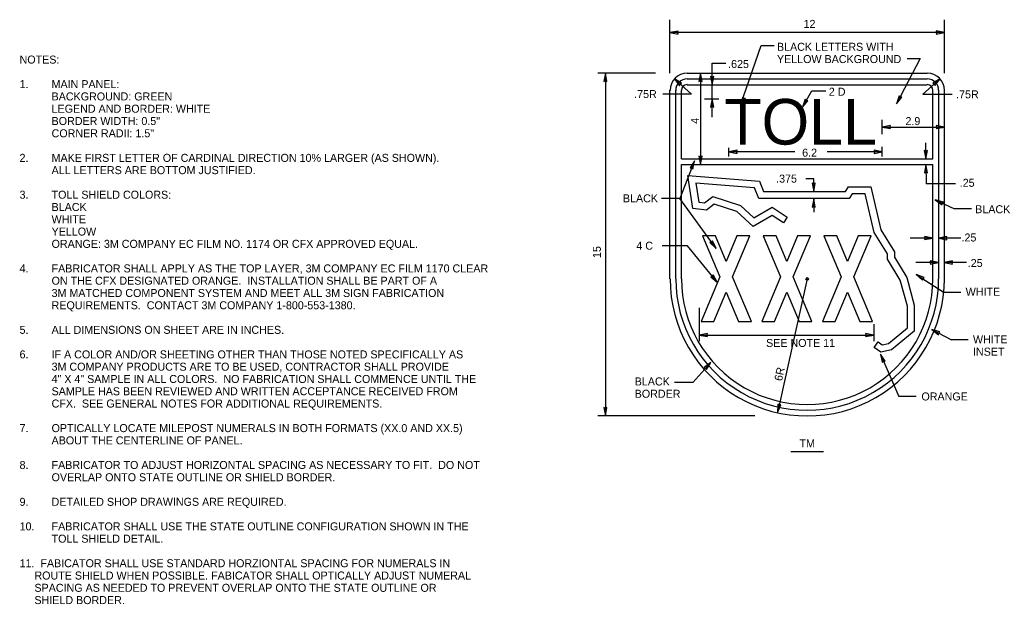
# Model space of a CAD drawing. Extents: x 56108 to 56734, y 11696 to 12110.
# Drawn here: x 56150 to 56496.4, y 11904.3 to 12108.8 of the extents above; entities that cross this region are included whole.
import ezdxf

# ---------------------------------------------------------------- set-up
doc = ezdxf.new("R2010")
doc.units = 0
for name, color, linetype in [('GSDims', 7, 'Continuous'), ('SignDetail', 7, 'Continuous'), ('SignPanel', 7, 'Continuous'), ('TextNotes', 7, 'Continuous')]:
    doc.layers.add(name, color=color, linetype=linetype)

msp = doc.modelspace()

# ---------------------------------------------------------------- linework, layer by layer
at = {"layer": 'GSDims'}
for p, q in [((56377.39, 12090.18), (56377.39, 12108.84)), ((56473.39, 12090.18), (56473.39, 12108.84)), ((56380.29, 12104.92), (56377.39, 12104.38)), ((56473.39, 12104.38), (56377.39, 12104.38)), ((56377.39, 12104.38), (56380.29, 12103.82)), ((56380.07, 12104.38), (56380.29, 12104.92)), ((56380.29, 12103.82), (56380.07, 12104.38)), ((56473.39, 12104.38), (56470.49, 12104.94)), ((56470.49, 12104.94), (56470.71, 12104.38)), ((56470.71, 12104.38), (56470.49, 12103.84)), ((56470.49, 12103.84), (56473.39, 12104.38)), ((56402.04, 12078.92), (56409.31, 12099.87)), ((56409.31, 12099.87), (56413.81, 12099.87)), ((56392.14, 12086.14), (56392.14, 12093.7)), ((56392.14, 12093.7), (56396.87, 12093.7)), ((56464.86, 12095.25), (56456.65, 12079.44)), ((56460.36, 12095.25), (56464.86, 12095.25)), ((56372.28, 12090.18), (56352.1, 12090.18)), ((56354.78, 12090.18), (56354.22, 12087.28)), ((56354.78, 12090.18), (56354.78, 11970.18)), ((56355.32, 12087.28), (56354.78, 12090.18)), ((56388.08, 12090.18), (56387.52, 12087.28)), ((56388.08, 12090.18), (56388.08, 12058.17)), ((56388.62, 12087.28), (56388.08, 12090.18)), ((56473.39, 12090.18), (56473.39, 12090.18)), ((56354.22, 12087.28), (56354.78, 12087.5)), ((56354.78, 12087.5), (56355.32, 12087.28)), ((56378.93, 12088.14), (56384.95, 12082.78)), ((56378.93, 12088.14), (56380.72, 12085.79)), ((56381.45, 12086.61), (56378.93, 12088.14)), ((56380.93, 12086.36), (56381.45, 12086.61)), ((56387.52, 12087.28), (56388.08, 12087.5)), ((56388.08, 12087.5), (56388.62, 12087.28)), ((56392.14, 12088.82), (56391.6, 12089.04)), ((56391.6, 12089.04), (56392.14, 12086.14)), ((56392.14, 12086.14), (56392.7, 12089.04)), ((56392.7, 12089.04), (56392.14, 12088.82)), ((56471.86, 12088.14), (56465.84, 12082.78)), ((56471.86, 12088.14), (56469.32, 12086.63)), ((56469.32, 12086.63), (56469.85, 12086.36)), ((56470.05, 12085.81), (56471.86, 12088.14)), ((56380.72, 12085.79), (56380.93, 12086.36)), ((56392.14, 12081.15), (56392.14, 12086.14)), ((56423.71, 12078.3), (56427, 12083.96)), ((56427, 12083.96), (56431.94, 12083.96)), ((56469.85, 12086.36), (56470.05, 12085.81)), ((56384.95, 12082.78), (56374.94, 12082.78)), ((56389.51, 12081.15), (56394.52, 12081.15)), ((56392.14, 12081.15), (56391.58, 12078.25)), ((56392.14, 12074.77), (56392.14, 12081.15)), ((56392.68, 12078.25), (56392.14, 12081.15)), ((56402.78, 12081.78), (56402.04, 12078.92)), ((56402.04, 12078.92), (56403.78, 12081.31)), ((56403.18, 12081.35), (56402.78, 12081.78)), ((56403.78, 12081.31), (56403.18, 12081.35)), ((56424.7, 12081.08), (56423.71, 12078.3)), ((56423.71, 12078.3), (56425.65, 12080.52)), ((56425.06, 12080.62), (56424.7, 12081.08)), ((56425.65, 12080.52), (56425.06, 12080.62)), ((56457.51, 12082.26), (56456.65, 12079.44)), ((56456.65, 12079.44), (56458.48, 12081.75)), ((56457.88, 12081.82), (56457.51, 12082.26)), ((56458.48, 12081.75), (56457.88, 12081.82)), ((56465.84, 12082.78), (56476.15, 12082.78)), ((56391.58, 12078.25), (56392.14, 12078.47)), ((56392.14, 12078.47), (56392.68, 12078.25)), ((56451.66, 12068.8), (56451.66, 12073.81)), ((56454.56, 12071.86), (56451.66, 12071.32)), ((56451.66, 12071.32), (56473.39, 12071.32)), ((56451.66, 12071.32), (56454.56, 12070.76)), ((56454.34, 12071.32), (56454.56, 12071.86)), ((56454.56, 12070.76), (56454.34, 12071.32)), ((56473.39, 12071.32), (56470.49, 12071.88)), ((56470.49, 12071.88), (56470.71, 12071.32)), ((56470.71, 12071.32), (56470.49, 12070.78)), ((56470.49, 12070.78), (56473.39, 12071.32)), ((56466.89, 12060.16), (56466.84, 12065.75)), ((56397.98, 12061.05), (56397.98, 12064.02)), ((56400.88, 12063.17), (56397.98, 12062.63)), ((56421.03, 12062.63), (56397.98, 12062.63)), ((56397.98, 12062.63), (56400.88, 12062.07)), ((56400.66, 12062.63), (56400.88, 12063.17)), ((56400.88, 12062.07), (56400.66, 12062.63)), ((56451.66, 12062.63), (56432.42, 12062.63)), ((56451.66, 12062.63), (56448.76, 12063.19)), ((56448.76, 12063.19), (56448.98, 12062.63)), ((56448.98, 12062.63), (56448.76, 12062.09)), ((56448.76, 12062.09), (56451.66, 12062.63)), ((56451.66, 12061.05), (56451.66, 12064.36)), ((56466.87, 12062.84), (56466.33, 12063.05)), ((56466.33, 12063.05), (56466.89, 12060.16)), ((56467.43, 12063.06), (56466.87, 12062.84)), ((56466.89, 12060.16), (56467.43, 12063.06)), ((56386, 12059.49), (56380.84, 12046.35)), ((56386, 12059.49), (56384.42, 12056.99)), ((56385.44, 12056.59), (56386, 12059.49)), ((56388.08, 12060.85), (56387.54, 12061.07)), ((56387.54, 12061.07), (56388.08, 12058.17)), ((56388.08, 12058.17), (56388.64, 12061.07)), ((56388.64, 12061.07), (56388.08, 12060.85)), ((56384.42, 12056.99), (56385.02, 12056.99)), ((56385.02, 12056.99), (56385.44, 12056.59)), ((56466.89, 12058.17), (56466.36, 12055.26)), ((56466.36, 12055.26), (56466.92, 12055.49)), ((56466.89, 12058.17), (56466.96, 12051.4)), ((56467.46, 12055.27), (56466.89, 12058.17)), ((56466.92, 12055.49), (56467.46, 12055.27)), ((56427.66, 12053.16), (56424.9, 12053.16)), ((56427.66, 12048.77), (56427.66, 12053.16)), ((56396.89, 12050.73), (56396.89, 12050.73)), ((56427.66, 12051.45), (56427.12, 12051.67)), ((56427.12, 12051.67), (56427.66, 12048.77)), ((56427.66, 12048.77), (56428.22, 12051.67)), ((56428.22, 12051.67), (56427.66, 12051.45)), ((56477.25, 12051.4), (56466.96, 12051.4)), ((56380.84, 12046.35), (56374.46, 12046.35)), ((56393.51, 12028.8), (56380.84, 12046.35)), ((56427.66, 12046.18), (56427.13, 12043.27)), ((56427.66, 12046.18), (56427.72, 12041.47)), ((56428.23, 12043.28), (56427.66, 12046.18)), ((56470.19, 12045.79), (56476.95, 12042.63)), ((56470.19, 12045.79), (56472.58, 12044.05)), ((56473.04, 12045.05), (56470.19, 12045.79)), ((56472.61, 12044.66), (56473.04, 12045.05)), ((56427.13, 12043.27), (56427.69, 12043.5)), ((56427.69, 12043.5), (56428.23, 12043.28)), ((56472.58, 12044.05), (56472.61, 12044.66)), ((56482.8, 12042.63), (56476.95, 12042.63)), ((56391.94, 12030.97), (56391.38, 12030.84)), ((56392.27, 12031.48), (56391.94, 12030.97)), ((56393.51, 12028.8), (56392.27, 12031.48)), ((56469.36, 12032.44), (56461.45, 12032.44)), ((56469.36, 12032.44), (56466.46, 12033)), ((56466.46, 12033), (56466.68, 12032.44)), ((56466.68, 12032.44), (56466.46, 12031.9)), ((56466.46, 12031.9), (56469.36, 12032.44)), ((56474.28, 12032.98), (56471.38, 12032.44)), ((56479.17, 12032.44), (56471.38, 12032.44)), ((56471.38, 12032.44), (56474.28, 12031.88)), ((56474.06, 12032.44), (56474.28, 12032.98)), ((56474.28, 12031.88), (56474.06, 12032.44)), ((56383.54, 12029.72), (56374.71, 12029.72)), ((56393.94, 12017.02), (56383.54, 12029.72)), ((56391.38, 12030.84), (56393.51, 12028.8)), ((56471.3, 12023.88), (56468.4, 12024.44)), ((56468.4, 12024.44), (56468.62, 12023.88)), ((56476.22, 12024.42), (56473.32, 12023.88)), ((56476, 12023.88), (56476.22, 12024.42)), ((56471.3, 12023.88), (56463.39, 12023.88)), ((56468.62, 12023.88), (56468.4, 12023.34)), ((56468.4, 12023.34), (56471.3, 12023.88)), ((56481.12, 12023.88), (56473.32, 12023.88)), ((56473.32, 12023.88), (56476.22, 12023.32)), ((56476.22, 12023.32), (56476, 12023.88)), ((56425.42, 12018.14), (56414.96, 11971.3)), ((56463.53, 12019.72), (56473.31, 12013.44)), ((56463.53, 12019.72), (56465.66, 12017.68)), ((56466.26, 12018.61), (56463.53, 12019.72)), ((56465.66, 12017.68), (56465.78, 12018.27)), ((56465.78, 12018.27), (56466.26, 12018.61)), ((56479.16, 12013.44), (56473.31, 12013.44)), ((56387.65, 12008.05), (56387.65, 11996.3)), ((56448.65, 12002.28), (56448.65, 11996.3)), ((56469, 12000.47), (56475.85, 11996.79)), ((56469, 12000.47), (56471.29, 11998.6)), ((56471.81, 11999.57), (56469, 12000.47)), ((56390.55, 11999.05), (56387.65, 11998.51)), ((56387.65, 11998.51), (56448.65, 11998.51)), ((56387.65, 11998.51), (56390.55, 11997.95)), ((56390.33, 11998.51), (56390.55, 11999.05)), ((56390.55, 11997.95), (56390.33, 11998.51)), ((56448.65, 11998.51), (56445.75, 11999.07)), ((56445.75, 11999.07), (56445.97, 11998.51)), ((56445.97, 11998.51), (56445.75, 11997.97)), ((56445.75, 11997.97), (56448.65, 11998.51)), ((56471.29, 11998.6), (56471.36, 11999.2)), ((56471.36, 11999.2), (56471.81, 11999.57)), ((56481.7, 11996.79), (56475.85, 11996.79)), ((56450.97, 11991.85), (56457.44, 11977)), ((56450.97, 11991.85), (56451.62, 11988.97)), ((56452.62, 11989.41), (56450.97, 11991.85)), ((56451.62, 11988.97), (56452.04, 11989.39)), ((56452.04, 11989.39), (56452.62, 11989.41)), ((56391.67, 11988.92), (56385.34, 11981.9)), ((56391.67, 11988.92), (56389.32, 11987.14)), ((56389.32, 11987.14), (56389.88, 11986.93)), ((56389.88, 11986.93), (56390.13, 11986.41)), ((56390.13, 11986.41), (56391.67, 11988.92)), ((56385.34, 11981.9), (56378.97, 11981.9)), ((56463.48, 11977), (56457.44, 11977)), ((56354.78, 11972.86), (56354.24, 11973.08)), ((56354.24, 11973.08), (56354.78, 11970.18)), ((56354.78, 11970.18), (56355.34, 11973.08)), ((56355.34, 11973.08), (56354.78, 11972.86)), ((56415.06, 11974.25), (56414.96, 11971.3)), ((56414.96, 11971.3), (56416.14, 11974.01)), ((56415.54, 11973.92), (56415.06, 11974.25)), ((56416.14, 11974.01), (56415.54, 11973.92)), ((56407.11, 11970.18), (56352.1, 11970.18)), ((56431.13, 11957.66), (56419.65, 11957.66))]:
    msp.add_line(p, q, dxfattribs=at)
at = {"layer": 'SignDetail'}
for p, q in [((56383.39, 12090.18), (56467.39, 12090.18)), ((56383.39, 12088.16), (56467.39, 12088.16)), ((56377.39, 12018.14), (56377.39, 12084.18)), ((56379.41, 12018.14), (56379.41, 12084.18)), ((56381.37, 12060.18), (56381.37, 12084.18)), ((56383.39, 12086.14), (56467.39, 12086.14)), ((56469.36, 12060.18), (56469.36, 12084.18)), ((56471.38, 12018.14), (56471.38, 12084.18)), ((56473.39, 12018.14), (56473.39, 12084.18)), ((56381.37, 12060.18), (56469.36, 12060.18)), ((56381.37, 12018.14), (56381.37, 12058.17)), ((56381.37, 12058.17), (56469.36, 12058.17)), ((56469.36, 12018.14), (56469.36, 12058.17)), ((56393.29, 12033.22), (56388.8, 12033.22)), ((56388.8, 12033.22), (56394.81, 12018.86)), ((56397.06, 12024.22), (56393.29, 12033.22)), ((56400.83, 12033.22), (56397.06, 12024.22)), ((56399.31, 12018.86), (56405.32, 12033.22)), ((56405.32, 12033.22), (56400.83, 12033.22)), ((56414.5, 12033.22), (56410.01, 12033.22)), ((56410.01, 12033.22), (56416.02, 12018.86)), ((56418.27, 12024.22), (56414.5, 12033.22)), ((56422.04, 12033.22), (56418.27, 12024.22)), ((56420.52, 12018.86), (56426.53, 12033.22)), ((56426.53, 12033.22), (56422.04, 12033.22)), ((56435.71, 12033.22), (56431.22, 12033.22)), ((56431.22, 12033.22), (56437.23, 12018.86)), ((56439.48, 12024.22), (56435.71, 12033.22)), ((56443.25, 12033.22), (56439.48, 12024.22)), ((56441.73, 12018.86), (56447.74, 12033.22)), ((56447.74, 12033.22), (56443.25, 12033.22)), ((56394.81, 12018.86), (56388.27, 12003.22)), ((56392.24, 12019.09), (56391.68, 12018.92)), ((56391.68, 12018.92), (56393.94, 12017.02)), ((56392.53, 12019.62), (56392.24, 12019.09)), ((56393.94, 12017.02), (56392.53, 12019.62)), ((56405.85, 12003.22), (56399.31, 12018.86)), ((56416.02, 12018.86), (56409.48, 12003.22)), ((56427.06, 12003.22), (56420.52, 12018.86)), ((56437.23, 12018.86), (56430.69, 12003.22)), ((56448.27, 12003.22), (56441.73, 12018.86)), ((56392.77, 12003.22), (56397.06, 12013.49)), ((56397.06, 12013.49), (56401.36, 12003.22)), ((56413.97, 12003.22), (56418.27, 12013.49)), ((56418.27, 12013.49), (56422.57, 12003.22)), ((56435.18, 12003.22), (56439.48, 12013.49)), ((56439.48, 12013.49), (56443.78, 12003.22)), ((56388.27, 12003.22), (56392.77, 12003.22)), ((56401.36, 12003.22), (56405.85, 12003.22)), ((56409.48, 12003.22), (56413.97, 12003.22)), ((56422.57, 12003.22), (56427.06, 12003.22)), ((56430.69, 12003.22), (56435.18, 12003.22)), ((56443.78, 12003.22), (56448.27, 12003.22))]:
    msp.add_line(p, q, dxfattribs=at)
for points in [[(56413.97, 12003.22), (56418.27, 12013.49), (56422.57, 12003.22), (56427.06, 12003.22), (56420.52, 12018.86), (56426.53, 12033.22), (56422.04, 12033.22), (56418.27, 12024.22), (56414.5, 12033.22), (56410.01, 12033.22), (56416.02, 12018.86), (56409.48, 12003.22)], [(56435.18, 12003.22), (56439.48, 12013.49), (56443.78, 12003.22), (56448.27, 12003.22), (56441.73, 12018.86), (56447.74, 12033.22), (56443.25, 12033.22), (56439.48, 12024.22), (56435.71, 12033.22), (56431.22, 12033.22), (56437.23, 12018.86), (56430.69, 12003.22)]]:
    msp.add_lwpolyline(points, close=True, dxfattribs=at)
msp.add_circle((56425.42, 12018.14), 0.455, dxfattribs=at)
for centre, major_axis, start_param, end_param in [((56383.41, 12084.15), (0, 6), 0, 1.570796), ((56467.37, 12084.15), (0, 6), 4.712389, 6.283185), ((56383.41, 12084.15), (0, 4), 0, 1.570796), ((56467.37, 12084.15), (0, 4), 4.712389, 6.283185), ((56383.41, 12084.15), (0, 2), 0, 1.570796), ((56467.37, 12084.15), (0, 2), 4.712389, 6.283185), ((56425.39, 12018.17), (0, -47.99), 4.712389, 7.853982), ((56425.39, 12018.17), (0, -45.99), 4.712389, 7.853982), ((56425.39, 12018.17), (0, -43.99), 4.712389, 7.853982)]:
    msp.add_ellipse(centre, major_axis=major_axis, ratio=0.9997, start_param=start_param, end_param=end_param, dxfattribs=at)
at = {"layer": 'SignPanel'}
for p, q in [((56385.42, 12042.85), (56383.64, 12054.3)), ((56383.64, 12054.3), (56408.68, 12052.37)), ((56408.68, 12052.37), (56410.08, 12048.77)), ((56406.98, 12050.08), (56386.49, 12051.66)), ((56386.49, 12051.66), (56387.53, 12045.02)), ((56408.43, 12046.35), (56406.98, 12050.08)), ((56410.08, 12048.77), (56438.81, 12048.77)), ((56438.81, 12048.77), (56439.89, 12050.37)), ((56439.89, 12050.37), (56447.62, 12050.37)), ((56447.62, 12050.37), (56451.12, 12035.31)), ((56387.53, 12045.02), (56389.51, 12044.77)), ((56389.51, 12044.77), (56392.36, 12047.01)), ((56392.36, 12047.01), (56402.02, 12043.87)), ((56440.09, 12046.35), (56408.43, 12046.35)), ((56441.17, 12047.95), (56440.09, 12046.35)), ((56445.7, 12047.95), (56441.17, 12047.95)), ((56448.85, 12034.38), (56445.7, 12047.95)), ((56390.21, 12042.25), (56385.42, 12042.85)), ((56392.84, 12044.32), (56390.21, 12042.25)), ((56400.77, 12041.74), (56392.84, 12044.32)), ((56406.44, 12036.48), (56400.77, 12041.74)), ((56402.02, 12043.87), (56406.76, 12039.48)), ((56406.76, 12039.48), (56413.19, 12043.25)), ((56413.19, 12043.25), (56418.42, 12039.72)), ((56413.1, 12040.4), (56406.44, 12036.48)), ((56417.07, 12037.72), (56413.1, 12040.4)), ((56418.42, 12039.72), (56417.07, 12037.72)), ((56451.12, 12035.31), (56455.88, 12027.66)), ((56453.46, 12026.97), (56448.85, 12034.38)), ((56455.88, 12027.66), (56455.88, 12025.73)), ((56453.46, 12025.05), (56453.46, 12026.97)), ((56457.95, 12017.67), (56453.46, 12025.05)), ((56455.88, 12025.73), (56460.19, 12018.63)), ((56460.42, 12008.6), (56457.95, 12017.67)), ((56460.19, 12018.63), (56462.84, 12008.93)), ((56460.42, 12001), (56460.42, 12008.6)), ((56462.84, 12008.93), (56462.84, 11999.86)), ((56453.83, 11995.59), (56460.42, 12001)), ((56462.84, 11999.86), (56454.93, 11993.37)), ((56448.79, 11994.12), (56450.17, 11996.11)), ((56451.17, 11992.47), (56448.79, 11994.12)), ((56450.17, 11996.11), (56451.66, 11995.07)), ((56454.93, 11993.37), (56451.17, 11992.47)), ((56451.66, 11995.07), (56453.83, 11995.59))]:
    msp.add_line(p, q, dxfattribs=at)

# ---------------------------------------------------------------- texts
at = {"layer": 'GSDims'}
for s, p in [('12', (56424.12, 12106.01)), ('BLACK LETTERS WITH', (56414.81, 12098)), ('.625', (56397.72, 12091.97)), ('YELLOW BACKGROUND', (56414.81, 12093.7)), ('.75R', (56364.86, 12081.45)), ('2 D', (56432.95, 12082.27)), ('.75R', (56477.47, 12081.36)), ('2.9', (56459.75, 12071.99)), ('6.2', (56423.62, 12060.94)), ('.375', (56414.52, 12051.85)), ('.25', (56478.74, 12050.4)), ('BLACK', (56360.93, 12044.95)), ('BLACK', (56484.15, 12041.14)), ('4 C', (56365.63, 12028.37)), ('.25', (56479.36, 12031.25)), ('.25', (56481.56, 12022.31)), ('WHITE', (56480.82, 12012.23)), ('SEE NOTE 11', (56411, 11994.33)), ('WHITE', (56483.37, 11995.58)), ('INSET', (56483.37, 11991.28)), ('BLACK', (56365.05, 11980.85)), ('BORDER', (56365.05, 11976.55)), ('ORANGE', (56465.34, 11975.6)), ('TM', (56422.69, 11959.16))]:
    msp.add_text(s, height=2.8, dxfattribs=at).set_placement(p)
for s, rotation, p in [('4', 90, (56387.52, 12072.44)), ('15', 90, (56353.22, 12025.47)), ('6R', 77.7388, (56416.56, 11982.22))]:
    msp.add_text(s, height=2.8, rotation=rotation, dxfattribs=at).set_placement(p)
at = {"layer": 'SignDetail'}
msp.add_text('TOLL', height=15.981, dxfattribs=at).set_placement((56396.39, 12065.16))
at = {"layer": 'TextNotes'}
for s, p in [('NOTES:', (56149.89, 12093.52)), ('1.', (56149.89, 12084.92)), ('MAIN PANEL:', (56161.09, 12084.92)), ('BACKGROUND: GREEN', (56161.09, 12080.62)), ('LEGEND AND BORDER: WHITE', (56161.09, 12076.32)), ('BORDER WIDTH: 0.5"', (56161.09, 12072.02)), ('CORNER RADII: 1.5"', (56161.09, 12067.72)), ('2.', (56149.89, 12059.12)), ('MAKE FIRST LETTER OF CARDINAL DIRECTION 10% LARGER (AS SHOWN).', (56161.09, 12059.12)), ('ALL LETTERS ARE BOTTOM JUSTIFIED.', (56161.09, 12054.82)), ('3.', (56149.89, 12046.22)), ('TOLL SHIELD COLORS:', (56161.09, 12046.22)), ('BLACK', (56161.09, 12041.92)), ('WHITE', (56161.09, 12037.62)), ('YELLOW', (56161.09, 12033.32)), ('ORANGE: 3M COMPANY EC FILM NO. 1174 OR CFX APPROVED EQUAL.', (56161.09, 12029.02)), ('4.', (56149.89, 12020.42)), ('FABRICATOR SHALL APPLY AS THE TOP LAYER, 3M COMPANY EC FILM 1170 CLEAR', (56161.09, 12020.42)), ('ON THE CFX DESIGNATED ORANGE.  INSTALLATION SHALL BE PART OF A ', (56161.09, 12016.12)), ('3M MATCHED COMPONENT SYSTEM AND MEET ALL 3M SIGN FABRICATION ', (56161.09, 12011.82)), ('REQUIREMENTS.  CONTACT 3M COMPANY 1-800-553-1380.', (56161.09, 12007.52)), ('5.', (56149.89, 11998.92)), ('ALL DIMENSIONS ON SHEET ARE IN INCHES.', (56161.09, 11998.92)), ('6.', (56149.89, 11990.32)), ('IF A COLOR AND/OR SHEETING OTHER THAN THOSE NOTED SPECIFICALLY AS ', (56161.09, 11990.32)), ('3M COMPANY PRODUCTS ARE TO BE USED, CONTRACTOR SHALL PROVIDE', (56161.09, 11986.02)), ('4" X 4" SAMPLE IN ALL COLORS.  NO FABRICATION SHALL COMMENCE UNTIL THE ', (56161.09, 11981.72)), ('SAMPLE HAS BEEN REVIEWED AND WRITTEN ACCEPTANCE RECEIVED FROM', (56161.09, 11977.42)), ('CFX.  SEE GENERAL NOTES FOR ADDITIONAL REQUIREMENTS.', (56161.09, 11973.12)), ('7.', (56149.89, 11964.52)), ('OPTICALLY LOCATE MILEPOST NUMERALS IN BOTH FORMATS (XX.0 AND XX.5) ', (56161.09, 11964.52)), ('ABOUT THE CENTERLINE OF PANEL.', (56161.09, 11960.22)), ('8.', (56149.89, 11951.62)), ('FABRICATOR TO ADJUST HORIZONTAL SPACING AS NECESSARY TO FIT.  DO NOT', (56161.09, 11951.62)), ('OVERLAP ONTO STATE OUTLINE OR SHIELD BORDER.', (56161.09, 11947.32)), ('9.', (56149.89, 11938.72)), ('DETAILED SHOP DRAWINGS ARE REQUIRED.', (56161.09, 11938.72)), ('10.', (56149.89, 11930.12)), ('FABRICATOR SHALL USE THE STATE OUTLINE CONFIGURATION SHOWN IN THE', (56161.09, 11930.12)), ('TOLL SHIELD DETAIL.', (56161.09, 11925.82)), ('11.  FABICATOR SHALL USE STANDARD HORZIONTAL SPACING FOR NUMERALS IN ', (56149.89, 11917.22)), ('     ROUTE SHIELD WHEN POSSIBLE. FABICATOR SHALL OPTICALLY ADJUST NUMERAL ', (56149.89, 11912.92)), ('     SPACING AS NEEDED TO PREVENT OVERLAP ONTO THE STATE OUTLINE OR ', (56149.89, 11908.62)), ('     SHIELD BORDER.', (56149.89, 11904.32))]:
    msp.add_text(s, height=2.8, dxfattribs=at).set_placement(p)

doc.saveas('drawing.dxf')
